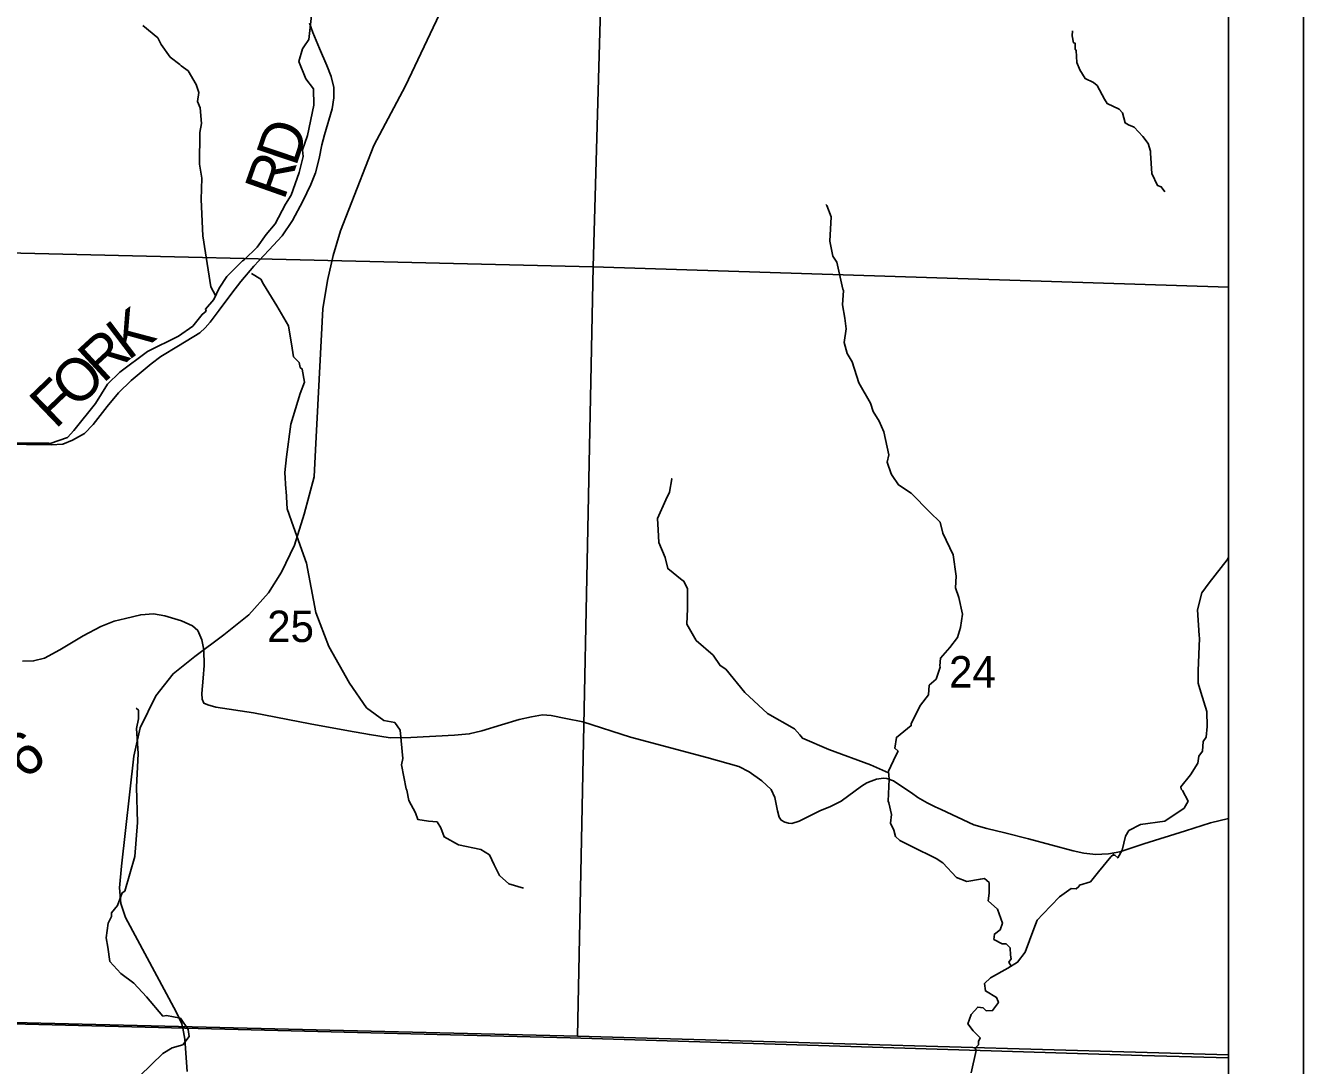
# Model space of a CAD drawing. Extents: x 0 to 34, y 0 to 22.
# Drawn here: x 7.298 to 9, y 16.238 to 17.624 of the extents above; entities that cross this region are included whole.
import ezdxf

# ---------------------------------------------------------------- set-up
doc = ezdxf.new("R2010")
doc.units = 0
for name, color, linetype in [('GM_X_Corporation', 7, 'Continuous'), ('GM_X_County_Road', 7, 'Continuous'), ('GM_X_County_Road_Text', 7, 'Continuous'), ('GM_X_Minor_River', 7, 'Continuous'), ('GM_X_Rail_Line', 7, 'Continuous'), ('GM_X_Section_Text', 7, 'Continuous'), ('GM_X_Township_Road', 7, 'Continuous'), ('GM_X_Township_Road_Text', 7, 'Continuous'), ('SH_Data', 7, 'Continuous')]:
    doc.layers.add(name, color=color, linetype=linetype)

msp = doc.modelspace()

# ---------------------------------------------------------------- linework, layer by layer
at = {"layer": 'GM_X_Corporation'}
for points in [[(4.9914, 16.3477), (5.6931, 16.3352), (5.9938, 16.3204), (6.9309, 16.303), (7.0302, 16.2995), (7.0491, 16.2993), (8.0233, 16.275), (8.785, 16.2515), (8.9, 16.2485), (8.9, 20.9), (2.1, 20.9)], [(8.9, 14.5591), (8.9, 16.2485), (8.785, 16.2515), (8.0233, 16.275), (7.0491, 16.2993), (7.0302, 16.2995), (6.9309, 16.303), (5.9938, 16.3204), (5.6931, 16.3352), (4.9914, 16.3477), (4.4958, 16.358), (3.9899, 16.3631), (3.7537, 16.3728), (3.6165, 16.3686), (3.0057, 16.3809), (2.7707, 16.392), (2.3623, 16.41), (2.2605, 16.4147), (2.1155, 16.4201), (2.1, 15.9517)], [(8.9, 14.1), (8.9, 16.2485), (8.785, 16.2515), (8.0233, 16.275), (7.0491, 16.2993), (7.0302, 16.2995), (6.9309, 16.303), (5.9938, 16.3204), (5.6931, 16.3352), (4.9914, 16.3477)]]:
    msp.add_lwpolyline(points, dxfattribs=at)
for points in [[(8.9, 16.2485), (8.9, 20.9), (7.1302, 20.9), (7.1249, 20.7061), (7.1008, 19.81), (7.0876, 19.4092), (7.0729, 18.3402), (7.0442, 17.0463), (7.0361, 16.5712), (7.0342, 16.5147), (7.0339, 16.4517), (7.0334, 16.423), (7.0337, 16.3927), (7.0306, 16.367), (7.0302, 16.2995), (7.0491, 16.2993), (8.0233, 16.275), (8.785, 16.2515)], [(7.0725, 18.3472), (8.0825, 18.3198), (8.0536, 17.3026), (7.0493, 17.3262)], [(8.9, 17.2751), (8.9, 18.2958), (8.0825, 18.3198), (8.0536, 17.3026)], [(8.0536, 17.3026), (8.0327, 16.2773), (7.0242, 16.3016), (7.0493, 17.3262)], [(8.9, 16.2525), (8.9, 17.2751), (8.0536, 17.3026), (8.0327, 16.2773)]]:
    msp.add_lwpolyline(points, close=True, dxfattribs=at)
at = {"layer": 'GM_X_County_Road'}
msp.add_lwpolyline([(7.2367, 17.0668), (7.2989, 17.0655), (7.3316, 17.065), (7.3472, 17.0662), (7.36, 17.0713), (7.3761, 17.0804), (7.3878, 17.0925), (7.4063, 17.1162), (7.4214, 17.1347), (7.4381, 17.1507), (7.4647, 17.1733), (7.4777, 17.183), (7.5012, 17.1969), (7.5298, 17.2143), (7.537, 17.2213), (7.5433, 17.2285), (7.5555, 17.2447), (7.5722, 17.2675), (7.5842, 17.2828), (7.6015, 17.3034), (7.6218, 17.3248), (7.6394, 17.3439), (7.6534, 17.3642), (7.6671, 17.3897), (7.6777, 17.4123), (7.6838, 17.4276), (7.6885, 17.4468), (7.6924, 17.4648), (7.6958, 17.4785), (7.7059, 17.513), (7.7084, 17.5275), (7.7082, 17.5414), (7.7048, 17.5561), (7.6991, 17.5705), (7.689, 17.5935), (7.6804, 17.6147), (7.6757, 17.6272)], dxfattribs=at)
at = {"layer": 'GM_X_Minor_River'}
for points in [[(7.2862, 17.0672), (7.3282, 17.0675), (7.3305, 17.0671), (7.3535, 17.075), (7.3619, 17.0841), (7.3907, 17.1204), (7.4067, 17.1461), (7.423, 17.162), (7.4601, 17.1895), (7.5014, 17.2102), (7.5203, 17.2231), (7.5328, 17.2389), (7.5381, 17.2431), (7.5374, 17.2461), (7.5484, 17.259), (7.5556, 17.2741), (7.5658, 17.2893), (7.5867, 17.3104), (7.589, 17.3119), (7.606, 17.3285), (7.6182, 17.3456), (7.6299, 17.3599), (7.644, 17.386), (7.6516, 17.3978), (7.6622, 17.428), (7.6672, 17.4492), (7.6665, 17.4583), (7.6733, 17.4773), (7.6818, 17.5178), (7.6811, 17.5397), (7.6709, 17.5527), (7.6615, 17.5758), (7.6664, 17.5928), (7.6683, 17.5955), (7.6748, 17.6053), (7.6794, 17.6451)], [(7.5508, 17.264), (7.5442, 17.2759), (7.5338, 17.3439), (7.5313, 17.392), (7.5325, 17.4205), (7.5295, 17.4394), (7.5297, 17.4815), (7.532, 17.4932), (7.5301, 17.5141), (7.5267, 17.5228), (7.5283, 17.5349), (7.5249, 17.5455), (7.514, 17.5634), (7.5049, 17.5702), (7.503, 17.5721), (7.4902, 17.582), (7.4781, 17.5987), (7.4736, 17.6074), (7.4536, 17.6242)], [(8.8155, 17.4022), (8.8106, 17.409), (8.8057, 17.4106), (8.7981, 17.4269), (8.7963, 17.4538), (8.7963, 17.4565), (8.7933, 17.4667), (8.7862, 17.4762), (8.7745, 17.4887), (8.7669, 17.4914), (8.7624, 17.4941), (8.759, 17.5077), (8.7545, 17.5123), (8.7383, 17.5199), (8.7349, 17.526), (8.7251, 17.5442), (8.7202, 17.548), (8.7092, 17.5533), (8.7021, 17.5651), (8.6983, 17.5746), (8.6972, 17.5905), (8.6957, 17.5924), (8.6961, 17.6003), (8.6935, 17.6011), (8.692, 17.6102), (8.6924, 17.6167)], [(8.6106, 16.3705), (8.6075, 16.376), (8.6105, 16.3802), (8.6098, 16.3851), (8.6091, 16.395), (8.6038, 16.4003), (8.5985, 16.4), (8.5875, 16.406), (8.5883, 16.4132), (8.5959, 16.4189), (8.5989, 16.4276), (8.5926, 16.4462), (8.5801, 16.4573), (8.5813, 16.4679), (8.5813, 16.469), (8.5813, 16.4819), (8.5749, 16.4872), (8.5696, 16.4865), (8.5514, 16.4831), (8.5378, 16.4885), (8.5197, 16.5082), (8.5107, 16.5139), (8.4782, 16.53), (8.4623, 16.538), (8.4567, 16.5433), (8.4541, 16.5516), (8.4499, 16.5608), (8.4511, 16.5725), (8.4477, 16.5881), (8.4466, 16.5903), (8.4482, 16.6195), (8.4471, 16.6305), (8.457, 16.6513), (8.46, 16.657), (8.4555, 16.6608), (8.4578, 16.6752), (8.4775, 16.6911), (8.4775, 16.6937), (8.49, 16.7183), (8.5003, 16.7319), (8.5015, 16.7448), (8.5109, 16.7531), (8.5159, 16.7687), (8.5155, 16.7709), (8.5163, 16.7808), (8.5288, 16.7952), (8.5391, 16.8084), (8.5432, 16.8217), (8.5456, 16.8395), (8.5411, 16.8618), (8.5366, 16.8744), (8.5374, 16.8903), (8.5333, 16.9187), (8.5194, 16.9476), (8.516, 16.962), (8.5021, 16.9753), (8.4772, 17.0008), (8.4606, 17.0118), (8.4523, 17.0243), (8.4508, 17.0266), (8.4455, 17.0422), (8.4478, 17.052), (8.4411, 17.0824), (8.4347, 17.0968), (8.4268, 17.1097), (8.4234, 17.1207), (8.4076, 17.1476), (8.399, 17.1757), (8.3922, 17.1871), (8.3881, 17.2015), (8.3908, 17.2197), (8.3889, 17.2341), (8.3859, 17.2519), (8.3871, 17.2709), (8.3864, 17.2728), (8.3785, 17.3088), (8.3729, 17.3168), (8.3691, 17.3365), (8.3707, 17.3691), (8.3651, 17.3842), (8.3639, 17.3854)], [(7.5984, 17.2933), (7.6108, 17.2861), (7.6146, 17.2793), (7.6323, 17.2504), (7.6477, 17.2238), (7.6526, 17.1939), (7.6544, 17.1825), (7.662, 17.1749), (7.6635, 17.1681), (7.6661, 17.1662), (7.6691, 17.1487), (7.6634, 17.1336), (7.6508, 17.0927), (7.6454, 17.0491), (7.6431, 17.0283), (7.6445, 17.0063), (7.6449, 17.0036), (7.646, 16.9801), (7.6546, 16.9558), (7.6719, 16.9073), (7.6842, 16.8417), (7.7018, 16.7965), (7.7293, 16.7475), (7.7519, 16.7148), (7.7749, 16.6977), (7.7893, 16.695), (7.7968, 16.6851), (7.8001, 16.6472), (7.7986, 16.6389), (7.8046, 16.6066), (7.8057, 16.6051), (7.8083, 16.5911), (7.817, 16.5748), (7.8203, 16.5657), (7.8343, 16.5637), (7.8457, 16.5629), (7.8509, 16.5546), (7.8551, 16.5428), (7.8743, 16.5321), (7.9042, 16.526), (7.9155, 16.5187), (7.9219, 16.5055), (7.929, 16.4914), (7.9415, 16.48), (7.9608, 16.4746)], [(8.4473, 16.6281), (8.4233, 16.6389), (8.3677, 16.6592), (8.3326, 16.6745), (8.3292, 16.6786), (8.3221, 16.6866), (8.2858, 16.7072), (8.2556, 16.7353), (8.2304, 16.7661), (8.2228, 16.7711), (8.2134, 16.7847), (8.1908, 16.8045), (8.1784, 16.8262), (8.1795, 16.8466), (8.1796, 16.8735), (8.1747, 16.8834), (8.1721, 16.8849), (8.1532, 16.9002), (8.1495, 16.9149), (8.1412, 16.9351), (8.1405, 16.9517), (8.1394, 16.9669), (8.1504, 16.9919), (8.1554, 17.0021), (8.1584, 17.0199), (8.1584, 17.0195)], [(8.5638, 16.2581), (8.5626, 16.2613), (8.5671, 16.2658), (8.5671, 16.27), (8.5694, 16.2749), (8.56, 16.2841), (8.5528, 16.2936), (8.5574, 16.3061), (8.5661, 16.3159), (8.5733, 16.3151), (8.5775, 16.3109), (8.5858, 16.3113), (8.5937, 16.3222), (8.5934, 16.3234), (8.5911, 16.3287), (8.5764, 16.3375), (8.5749, 16.3473), (8.5832, 16.3549), (8.606, 16.3677), (8.6192, 16.3756), (8.6291, 16.3892), (8.6409, 16.4203), (8.6451, 16.4317), (8.6527, 16.4396), (8.675, 16.463), (8.6906, 16.474), (8.697, 16.4736), (8.7008, 16.4766), (8.7015, 16.4785), (8.7163, 16.483), (8.7269, 16.4962), (8.7436, 16.5163), (8.747, 16.5193), (8.7455, 16.5178), (8.7489, 16.5185), (8.7527, 16.5147), (8.7584, 16.525), (8.763, 16.5435), (8.7672, 16.5511), (8.7831, 16.5594), (8.8152, 16.5635), (8.8413, 16.5812), (8.8463, 16.5903), (8.8388, 16.6047), (8.8373, 16.6062), (8.8365, 16.6093), (8.8494, 16.6255), (8.8593, 16.641), (8.8608, 16.6501), (8.8654, 16.6569), (8.8665, 16.6698), (8.8703, 16.6755), (8.8719, 16.6899), (8.8712, 16.71), (8.8633, 16.7354), (8.8596, 16.7476), (8.8596, 16.7642), (8.8616, 16.8074), (8.8609, 16.8112), (8.859, 16.8453), (8.8648, 16.8681), (8.8743, 16.8813), (8.8982, 16.9119), (8.9, 16.915)], [(7.5143, 16.286), (7.5039, 16.3012), (7.4854, 16.3047), (7.4805, 16.3039), (7.4586, 16.3298), (7.4416, 16.348), (7.4243, 16.3606), (7.4099, 16.3766), (7.407, 16.3959), (7.4051, 16.4084), (7.4074, 16.4277), (7.412, 16.4365), (7.412, 16.4414), (7.42, 16.4512), (7.4261, 16.4683), (7.4299, 16.4705), (7.4432, 16.5164), (7.4467, 16.5618), (7.4453, 16.6088), (7.4477, 16.654), (7.4452, 16.6873), (7.4482, 16.7002), (7.4479, 16.7116), (7.4449, 16.7142)], [(7.5143, 16.286), (7.5155, 16.2768), (7.5069, 16.2654), (7.4929, 16.2615), (7.4805, 16.2539), (7.4497, 16.2244), (7.4371, 16.1929), (7.4374, 16.1682), (7.4446, 16.1573), (7.4671, 16.1392), (7.537, 16.0999), (7.548, 16.0886), (7.5657, 16.0595), (7.5876, 16.0115), (7.5901, 15.9831), (7.5944, 15.971), (7.5938, 15.9486), (7.6112, 15.9063), (7.6182, 15.876)], [(8.5575, 16.2283), (8.5638, 16.2581)]]:
    msp.add_lwpolyline(points, dxfattribs=at)
at = {"layer": 'GM_X_Rail_Line'}
for points in [[(7.5069, 16.2878), (7.5058, 16.2935), (7.498, 16.3098), (7.4306, 16.4355), (7.4247, 16.4538), (7.4227, 16.4748), (7.4253, 16.5036), (7.4417, 16.6502), (7.4502, 16.6882), (7.4712, 16.7307), (7.4941, 16.7602), (7.5229, 16.7831), (7.5615, 16.8119), (7.5949, 16.8387), (7.621, 16.8681), (7.6387, 16.8956), (7.6557, 16.9316), (7.6688, 16.9728), (7.6819, 17.0226), (7.6839, 17.0586), (7.6937, 17.2464), (7.6996, 17.2843), (7.7074, 17.3177), (7.7172, 17.3504), (7.7617, 17.4642), (7.8036, 17.5434), (7.8821, 17.7088)], [(7.513, 16.23), (7.5097, 16.2732), (7.5069, 16.2878)]]:
    msp.add_lwpolyline(points, dxfattribs=at)
at = {"layer": 'GM_X_Township_Road'}
msp.add_lwpolyline([(7.2933, 16.7769), (7.3082, 16.7772), (7.3226, 16.7807), (7.3434, 16.7918), (7.3745, 16.8105), (7.3977, 16.8229), (7.4155, 16.8301), (7.4308, 16.8339), (7.4511, 16.8387), (7.4678, 16.8398), (7.4829, 16.8373), (7.5055, 16.8306), (7.5201, 16.8239), (7.5271, 16.8177), (7.5325, 16.8055), (7.535, 16.7922), (7.5353, 16.7712), (7.5342, 16.7543), (7.5323, 16.7338), (7.533, 16.7262), (7.5352, 16.7208), (7.5406, 16.7186), (7.551, 16.7158), (7.6013, 16.7079), (7.6766, 16.6935), (7.7278, 16.684), (7.7557, 16.679), (7.7835, 16.6748), (7.8107, 16.675), (7.8689, 16.6781), (7.8886, 16.6799), (7.9054, 16.684), (7.9316, 16.6921), (7.9553, 16.6993), (7.9717, 16.7029), (7.9864, 16.7052), (7.9977, 16.7043), (8.0173, 16.7007), (8.04, 16.696), (8.1037, 16.6758), (8.2053, 16.6484), (8.2477, 16.6364), (8.2616, 16.6296), (8.2784, 16.6175), (8.291, 16.606), (8.2959, 16.5954), (8.2993, 16.5776), (8.3014, 16.569), (8.3043, 16.565), (8.309, 16.5623), (8.3138, 16.5609), (8.3184, 16.5606), (8.3284, 16.5636), (8.3558, 16.5776), (8.3698, 16.5831), (8.3843, 16.5904), (8.4113, 16.6103), (8.4184, 16.6149), (8.4242, 16.6172), (8.4313, 16.6196), (8.4406, 16.621), (8.4451, 16.6206), (8.4538, 16.6173), (8.4663, 16.6088), (8.4777, 16.6013), (8.4862, 16.5954), (8.4987, 16.588), (8.5092, 16.583), (8.5172, 16.5791), (8.5609, 16.5589), (8.578, 16.5539), (8.6022, 16.5483), (8.6336, 16.5402), (8.6933, 16.5242), (8.7074, 16.5212), (8.7236, 16.5194), (8.7313, 16.5196), (8.7401, 16.5203), (8.7552, 16.523), (8.7872, 16.5334), (8.8427, 16.5507), (8.8764, 16.5615), (8.9, 16.5671)], dxfattribs=at)
at = {"layer": 'SH_Data'}
for p, q in [((9, 21), (9, 14)), ((8.9, 20.9), (8.9, 14.1))]:
    msp.add_line(p, q, dxfattribs=at)

# ---------------------------------------------------------------- texts
at = {"layer": 'GM_X_County_Road_Text'}
for s, rotation, p in [('D', 71.3758, (7.6576, 17.4346)), ('R', 70.5554, (7.6418, 17.3897)), ('K', 37.111, (7.4341, 17.1767)), ('R', 42.6342, (7.4008, 17.146)), ('O', 43.8125, (7.365, 17.1116)), ('F', 43.8509, (7.3374, 17.0851))]:
    msp.add_text(s, height=0.0568, rotation=rotation, dxfattribs=at).set_placement(p)
at = {"layer": 'GM_X_Section_Text'}
for s, p in [('25', (7.6195, 16.8024)), ('24', (8.5279, 16.7418))]:
    msp.add_text(s, height=0.04186, rotation=0, dxfattribs=at).set_placement(p)
at = {"layer": 'GM_X_Township_Road_Text'}
msp.add_text('6', height=0.0568, rotation=34.3917, dxfattribs=at).set_placement((7.2939, 16.6183))

doc.saveas('drawing.dxf')
